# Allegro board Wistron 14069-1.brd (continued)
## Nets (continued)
GND: ATX1.3 ATX1.5 ATX1.7 ATX1.15 ATX1.17 ATX1.18 ATX1.19 ATX1.24 ATX2.1 ATX2.2 BT1.2 C2.2 C3.2 C6.2 C9.2 C11.2 C12.2 C13.2 C364.2 C365.2 C367.1 C371.2 C372.2 C420.1 C421.1 C422.1 C475.2 C476.2 C707.2 C708.2 C726.2 C727.2 C728.2 C729.2 C773.2 C774.2 C775.2 C1004.2 C1005.2 C1006.2 C1007.2 C1008.2 C1009.2 C1014.2 C1015.2 C1016.2 C1017.2 C1018.2 C1019.2 C1020.2 C1025.2 C1026.2 C1027.2 C1028.2 C1030.2 C1031.2 C1032.2 C1033.2 C1034.2 C1037.2 C1038.2 C1039.2 C1040.2 C1041.2 C1042.2 C1043.2 C1044.2 C1045.2 C1046.2 C1047.2 C1048.2 C1049.1 C1050.2 C1051.2 C1052.2 C1053.2 C1054.2 C1055.2 C1056.2 C1057.2 C1058.2 C1059.2 C1060.2 C1061.2 C1062.2 C1063.2 C1064.2 C1065.2 C1066.2 C1067.2 C1068.2 C1069.2 C1070.2 C1071.2 C1072.2 C1073.2 C1074.2 C1075.2 C1077.2 C1079.2 C1081.2 C1084.2 C1085.2 C1086.2 C1087.2 C1088.2 C1089.2 C1091.2 C1092.2 C1093.2 C1095.2 C1096.2 C1097.2 C1098.2 C1099.2 C1100.2 C1101.2 C1102.2 C1103.2 C1106.2 C1107.2 C1108.2 C1109.2 C1110.2 C1111.2 C1112.2 C1113.2 C1122.2 C1123.2 C1124.2 C1125.2 C1126.2 C1127.2 C1128.2 C1129.2 C1130.2 C1131.2 C1132.2 C1133.2 C1135.2 C1136.2 C1137.2 C1138.2 C1139.2 C1140.2 C1141.2 C1142.2 C1143.2 C1144.2 C1145.2 C1146.2 C1201.2 C1202.2 C1203.2 C1204.2 C1205.2 C1207.2 C1208.2 C1209.2 C1210.2 C1211.2 C1212.2 C1213.2 C1214.2 C1215.2 C1216.2 C1217.2 C1218.2 C1219.2 C1220.2 C1301.2 C1302.2 C1303.2 C1304.2 C1305.2 C1306.2 C1307.2 C1308.2 C1309.2 C1310.2 C1311.2 C1312.2 C1313.2 C1314.2 C1315.2 C1401.2 C1404.2 C1405.2 C1406.2 C1407.2 C1408.2 C1409.2 C1410.2 C1411.2 C1412.2 C1413.2 C1414.2 C1415.2 C1416.2 C1417.2 C1701.2 C1801.2 C1802.2 C1803.2 C1804.2 C2001.1 C2002.2 C2003.1 C2004.1 C2006.1 C2007.2 C2008.2 C2038.2 C2101.2 C2301.1 C2302.2 C2303.2 C2304.2 C2305.2 C2306.2 C2307.2 C2308.2 C2309.2 C2310.2 C2311.2 C2312.2 C2313.2 C2314.2 C2315.2 C2316.2 C2317.2 C2318.2 C2319.2 C2320.2 C2321.2 C2322.2 C2501.2 C2503.1 C2504.2 C2601.2 C2602.2 C2603.2 C2604.2 C2605.2 C2712.2 C2713.2 C2717.1 C2718.1 C2719.1 C2720.1 C2721.2 C2722.2 C2723.1 C2728.2 C2729.2 C2732.2 C2912.2 C2932.2 C3101.1 C3102.2 C3103.2 C3104.2 C3105.2 C3106.2 C3107.2 C3108.2 C3109.2 C3110.2 C3111.2 C3112.2 C3113.2 C3114.2 C3115.2 C3116.1 C3121.2 C3123.2 C3124.2 C3140.2 C3141.2 C3142.2 C3143.2 C3201.2 C3202.2 C3204.2 C3205.2 C3206.2 C3207.2 C3401.2 C3402.1 C3403.2 C3506.2 C3601.2 C3605.2 C3606.2 C3701.2 C3702.2 C3703.2 C3704.2 C3705.2 C3706.2 C3708.2 C3709.2 C3710.2 C3714.2 C3715.2 C3801.2 C3802.2 C3803.2 C3804.2 C3805.2 C3806.2 C3807.2 C3809.2 C3810.2 C3811.2 C3812.2 C3813.2 C3901.2 C3902.2 C3903.2 C3904.2 C4301.2 C4302.1 C4303.2 C4304.1 C4305.1 C4306.1 C4307.2 C4308.2 C4309.2 C4310.2 C4311.2 C5609.1 C5610.1 C5611.1 C5612.2 C5613.2 C5701.2 C5712.2 C5713.2 C6110.2 C6111.2 C6112.2 C6113.2 C6214.2 C6401.2 C6402.2 C6403.1 C6404.1 C6405.1 C6406.2 C7902.2 C7903.2 C7904.2 C7905.2 C7906.2 C7907.2 C7909.2 C7915.2 C7916.2 C7917.2 C7918.1 C7919.2 C7920.2 C7921.1 C9310.2 C9311.2 C9312.2 C9321.2 C9322.2 C9329.2 C9330.2 C9402.2 C9403.2 C9404.2 C9405.2 C9406.2 C9407.2 C9408.2 C9409.2 C9410.2 C9411.2 C9412.2 C9413.2 C9414.2 C9415.2 C9420.2 C9422.2 C9902.1 C15159.2 C15160.2 C15161.2 CPU1.A4 CPU1.A7 CPU1.A11 CPU1.A13 CPU1.A15 CPU1.A17 CPU1.A24 CPU1.AA3 CPU1.AA8 CPU1.AA33 CPU1.AB5 CPU1.AB39 CPU1.AC3 CPU1.AC6 CPU1.AC33 CPU1.AC34 CPU1.AC35 CPU1.AD1 CPU1.AD4 CPU1.AD6 CPU1.AD7 CPU1.AD8 CPU1.AD33 CPU1.AD36 CPU1.AD37 CPU1.AD38 CPU1.AD39 CPU1.AD40 CPU1.AE3 CPU1.AE5 CPU1.AE8 CPU1.AE33 CPU1.AE36 CPU1.AF1 CPU1.AF5 CPU1.AF8 CPU1.AF33 CPU1.AF36 CPU1.AF37 CPU1.AF40 CPU1.AG1 CPU1.AG2 CPU1.AG3 CPU1.AG4 CPU1.AG5 CPU1.AG8 CPU1.AG33 CPU1.AG36 CPU1.AH5 CPU1.AH8 CPU1.AH33 CPU1.AH36 CPU1.AH37 CPU1.AH38 CPU1.AH39 CPU1.AH40 CPU1.AJ1 CPU1.AJ4 CPU1.AJ5 CPU1.AJ8 CPU1.AJ31 CPU1.AJ32 CPU1.AJ33 CPU1.AJ34 CPU1.AJ35 CPU1.AJ36 CPU1.AK5 CPU1.AK6 CPU1.AK7 CPU1.AK8 CPU1.AK9 CPU1.AK10 CPU1.AK12 CPU1.AK13 CPU1.AK15 CPU1.AK16 CPU1.AK17 CPU1.AK18 CPU1.AK19 CPU1.AK20 CPU1.AK23 CPU1.AK25 CPU1.AK26 CPU1.AK28 CPU1.AK29 CPU1.AK30 CPU1.AK36 CPU1.AK37 CPU1.AK40 CPU1.AL1 CPU1.AL2 CPU1.AL3 CPU1.AL4 CPU1.AL5 CPU1.AL11 CPU1.AL14 CPU1.AL21 CPU1.AL24 CPU1.AL27 CPU1.AL30 CPU1.AL36 CPU1.AM5 CPU1.AM11 CPU1.AM14 CPU1.AM17 CPU1.AM19 CPU1.AM24 CPU1.AM27 CPU1.AM30 CPU1.AM31 CPU1.AM32 CPU1.AM33 CPU1.AM34 CPU1.AM35 CPU1.AM36 CPU1.AM37 CPU1.AM38 CPU1.AM39 CPU1.AM40 CPU1.AN1 CPU1.AN4 CPU1.AN5 CPU1.AN6 CPU1.AN7 CPU1.AN8 CPU1.AN9 CPU1.AN10 CPU1.AN11 CPU1.AN14 CPU1.AN16 CPU1.AN19 CPU1.AN22 CPU1.AN23 CPU1.AN24 CPU1.AN27 CPU1.AN30 CPU1.AN36 CPU1.AP5 CPU1.AP11 CPU1.AP14 CPU1.AP24 CPU1.AP27 CPU1.AP30 CPU1.AP36 CPU1.AP37 CPU1.AP40 CPU1.AR1 CPU1.AR2 CPU1.AR3 CPU1.AR4 CPU1.AR5 CPU1.AR11 CPU1.AR14 CPU1.AR16 CPU1.AR17 CPU1.AR18 CPU1.AR19 CPU1.AR20 CPU1.AR21 CPU1.AR22 CPU1.AR23 CPU1.AR24 CPU1.AR27 CPU1.AR30 CPU1.AR31 CPU1.AR32 CPU1.AR33 CPU1.AR34 CPU1.AR35 CPU1.AR36 CPU1.AT5 CPU1.AT6 CPU1.AT7 CPU1.AT8 CPU1.AT9 CPU1.AT10 CPU1.AT11 CPU1.AT12 CPU1.AT13 CPU1.AT14 CPU1.AT15 CPU1.AT17 CPU1.AT24 CPU1.AT25 CPU1.AT26 CPU1.AT27 CPU1.AT28 CPU1.AT29 CPU1.AT30 CPU1.AT31 CPU1.AT32 CPU1.AT34 CPU1.AT36 CPU1.AT37 CPU1.AT38 CPU1.AT39 CPU1.AT40 CPU1.AU1 CPU1.AU4 CPU1.AU5 CPU1.AU7 CPU1.AU25 CPU1.AU30 CPU1.AU34 CPU1.AV2 CPU1.AV5 CPU1.AV9 CPU1.AV26 CPU1.AV28 CPU1.AV30 CPU1.AV34 CPU1.AV38 CPU1.AW3 CPU1.AW5 CPU1.AW9 CPU1.AW30 CPU1.AW32 CPU1.AW34 CPU1.AW36 CPU1.AY3 CPU1.AY5 CPU1.AY7 CPU1.AY9 CPU1.AY27 CPU1.AY30 CPU1.B6 CPU1.B24 CPU1.B26 CPU1.B28 CPU1.B30 CPU1.B38 CPU1.C2 CPU1.C5 CPU1.C8 CPU1.C10 CPU1.C12 CPU1.C14 CPU1.C16 CPU1.C18 CPU1.C20 CPU1.C22 CPU1.C24 CPU1.C31 CPU1.C33 CPU1.C35 CPU1.C37 CPU1.D4 CPU1.D7 CPU1.D24 CPU1.D26 CPU1.D28 CPU1.D30 CPU1.D37 CPU1.D39 CPU1.D40 CPU1.E3 CPU1.E6 CPU1.E9 CPU1.E11 CPU1.E13 CPU1.E15 CPU1.E17 CPU1.E19 CPU1.E21 CPU1.E23 CPU1.E31 CPU1.E33 CPU1.E35 CPU1.E37 CPU1.F1 CPU1.F4 CPU1.F7 CPU1.F10 CPU1.F22 CPU1.F26 CPU1.F28 CPU1.F30 CPU1.F40 CPU1.G3 CPU1.G6 CPU1.G8 CPU1.G11 CPU1.G13 CPU1.G15 CPU1.G17 CPU1.G19 CPU1.G22 CPU1.G31 CPU1.G33 CPU1.H1 CPU1.H4 CPU1.H7 CPU1.H8 CPU1.H9 CPU1.H21 CPU1.H24 CPU1.H26 CPU1.H28 CPU1.H30 CPU1.H35 CPU1.H37 CPU1.H39 CPU1.J3 CPU1.J6 CPU1.J10 CPU1.J12 CPU1.J16 CPU1.J18 CPU1.J20 CPU1.J32 CPU1.J34 CPU1.K1 CPU1.K4 CPU1.K7 CPU1.K14 CPU1.K15 CPU1.K17 CPU1.K19 CPU1.K22 CPU1.K24 CPU1.K26 CPU1.K28 CPU1.K30 CPU1.K33 CPU1.K35 CPU1.K37 CPU1.K39 CPU1.L3 CPU1.L6 CPU1.L9 CPU1.L11 CPU1.L13 CPU1.L32 CPU1.M1 CPU1.M4 CPU1.M7 CPU1.M10 CPU1.M12 CPU1.M15 CPU1.M17 CPU1.M19 CPU1.M21 CPU1.M23 CPU1.M25 CPU1.M27 CPU1.M29 CPU1.M35 CPU1.M37 CPU1.M39 CPU1.N3 CPU1.N6 CPU1.N8 CPU1.N33 CPU1.P1 CPU1.P4 CPU1.P35 CPU1.P37 CPU1.P39 CPU1.R3 CPU1.R6 CPU1.R8 CPU1.R33 CPU1.T1 CPU1.T4 CPU1.T35 CPU1.T37 CPU1.T39 CPU1.U3 CPU1.U6 CPU1.U33 CPU1.V1 CPU1.V8 CPU1.V35 CPU1.V37 CPU1.V39 CPU1.W3 CPU1.W6 CPU1.W33 CPU1.Y5 CPU1.Y35 CPU1.Y37 CRF1.2 D2702.K DBGH1.8 DBGH1.12 DIMM1.2 DIMM1.4 DIMM1.6 DIMM1.9 DIMM1.11 DIMM1.13 DIMM1.15 DIMM1.17 DIMM1.20 DIMM1.22 DIMM1.24 DIMM1.26 DIMM1.28 DIMM1.31 DIMM1.33 DIMM1.35 DIMM1.37 DIMM1.39 DIMM1.42 DIMM1.44 DIMM1.46 DIMM1.48 DIMM1.50 DIMM1.53 DIMM1.55 DIMM1.57 DIMM1.94 DIMM1.96 DIMM1.98 DIMM1.101 DIMM1.103 DIMM1.105 DIMM1.107 DIMM1.109 DIMM1.112 DIMM1.114 DIMM1.116 DIMM1.118 DIMM1.120 DIMM1.123 DIMM1.125 DIMM1.127 DIMM1.129 DIMM1.131 DIMM1.134 DIMM1.136 DIMM1.138 DIMM1.140 DIMM1.147 DIMM1.149 DIMM1.151 DIMM1.154 DIMM1.156 DIMM1.158 DIMM1.160 DIMM1.162 DIMM1.165 DIMM1.167 DIMM1.169 DIMM1.171 DIMM1.173 DIMM1.176 DIMM1.178 DIMM1.180 DIMM1.182 DIMM1.184 DIMM1.187 DIMM1.189 DIMM1.191 DIMM1.193 DIMM1.195 DIMM1.198 DIMM1.200 DIMM1.202 DIMM1.238 DIMM1.239 DIMM1.241 DIMM1.243 DIMM1.246 DIMM1.248 DIMM1.250 DIMM1.252 DIMM1.254 DIMM1.257 DIMM1.259 DIMM1.261 DIMM1.263 DIMM1.265 DIMM1.268 DIMM1.270 DIMM1.272 DIMM1.274 DIMM1.276 DIMM1.279 DIMM1.281 DIMM1.283 DIMM2.2 DIMM2.4 DIMM2.6 DIMM2.9 DIMM2.11 DIMM2.13 DIMM2.15 DIMM2.17 DIMM2.20 DIMM2.22 DIMM2.24 DIMM2.26 DIMM2.28 DIMM2.31 DIMM2.33 DIMM2.35 DIMM2.37 DIMM2.39 DIMM2.42 DIMM2.44 DIMM2.46 DIMM2.48 DIMM2.50 DIMM2.53 DIMM2.55 DIMM2.57 DIMM2.94 DIMM2.96 DIMM2.98 DIMM2.101 DIMM2.103 DIMM2.105 DIMM2.107 DIMM2.109 DIMM2.112 DIMM2.114 DIMM2.116 DIMM2.118 DIMM2.120 DIMM2.123 DIMM2.125 DIMM2.127 DIMM2.129 DIMM2.131 DIMM2.134 DIMM2.136 DIMM2.138 DIMM2.147 DIMM2.149 DIMM2.151 DIMM2.154 DIMM2.156 DIMM2.158 DIMM2.160 DIMM2.162 DIMM2.165 DIMM2.167 DIMM2.169 DIMM2.171 DIMM2.173 DIMM2.176 DIMM2.178 DIMM2.180 DIMM2.182 DIMM2.184 DIMM2.187 DIMM2.189 DIMM2.191 DIMM2.193 DIMM2.195 DIMM2.198 DIMM2.200 DIMM2.202 DIMM2.238 DIMM2.239 DIMM2.241 DIMM2.243 DIMM2.246 DIMM2.248 DIMM2.250 DIMM2.252 DIMM2.254 DIMM2.257 DIMM2.259 DIMM2.261 DIMM2.263 DIMM2.265 DIMM2.268 DIMM2.270 DIMM2.272 DIMM2.274 DIMM2.276 DIMM2.279 DIMM2.281 DIMM2.283 DIMM3.2 DIMM3.4 DIMM3.6 DIMM3.9 DIMM3.11 DIMM3.13 DIMM3.15 DIMM3.17 DIMM3.20 DIMM3.22 DIMM3.24 DIMM3.26 DIMM3.28 DIMM3.31 DIMM3.33 DIMM3.35 DIMM3.37 DIMM3.39 DIMM3.42 DIMM3.44 DIMM3.46 DIMM3.48 DIMM3.50 DIMM3.53 DIMM3.55 DIMM3.57 DIMM3.94 DIMM3.96 DIMM3.98 DIMM3.101 DIMM3.103 DIMM3.105 DIMM3.107 DIMM3.109 DIMM3.112 DIMM3.114 DIMM3.116 DIMM3.118 DIMM3.120 DIMM3.123 DIMM3.125 DIMM3.127 DIMM3.129 DIMM3.131 DIMM3.134 DIMM3.136 DIMM3.138 DIMM3.139 DIMM3.140 DIMM3.147 DIMM3.149 DIMM3.151 DIMM3.154 DIMM3.156 DIMM3.158 DIMM3.160 DIMM3.162 DIMM3.165 DIMM3.167 DIMM3.169 DIMM3.171 DIMM3.173 DIMM3.176 DIMM3.178 DIMM3.180 DIMM3.182 DIMM3.184 DIMM3.187 DIMM3.189 DIMM3.191 DIMM3.193 DIMM3.195 DIMM3.198 DIMM3.200 DIMM3.202 DIMM3.238 DIMM3.239 DIMM3.241 DIMM3.243 DIMM3.246 DIMM3.248 DIMM3.250 DIMM3.252 DIMM3.254 DIMM3.257 DIMM3.259 DIMM3.261 DIMM3.263 DIMM3.265 DIMM3.268 DIMM3.270 DIMM3.272 DIMM3.274 DIMM3.276 DIMM3.279 DIMM3.281 DIMM3.283 DIMM4.2 DIMM4.4 DIMM4.6 DIMM4.9 DIMM4.11 DIMM4.13 DIMM4.15 DIMM4.17 DIMM4.20 DIMM4.22 DIMM4.24 DIMM4.26 DIMM4.28 DIMM4.31 DIMM4.33 DIMM4.35 DIMM4.37 DIMM4.39 DIMM4.42 DIMM4.44 DIMM4.46 DIMM4.48 DIMM4.50 DIMM4.53 DIMM4.55 DIMM4.57 DIMM4.94 DIMM4.96 DIMM4.98 DIMM4.101 DIMM4.103 DIMM4.105 DIMM4.107 DIMM4.109 DIMM4.112 DIMM4.114 DIMM4.116 DIMM4.118 DIMM4.120 DIMM4.123 DIMM4.125 DIMM4.127 DIMM4.129 DIMM4.131 DIMM4.134 DIMM4.136 DIMM4.138 DIMM4.139 DIMM4.147 DIMM4.149 DIMM4.151 DIMM4.154 DIMM4.156 DIMM4.158 DIMM4.160 DIMM4.162 DIMM4.165 DIMM4.167 DIMM4.169 DIMM4.171 DIMM4.173 DIMM4.176 DIMM4.178 DIMM4.180 DIMM4.182 DIMM4.184 DIMM4.187 DIMM4.189 DIMM4.191 DIMM4.193 DIMM4.195 DIMM4.198 DIMM4.200 DIMM4.202 DIMM4.238 DIMM4.239 DIMM4.241 DIMM4.243 DIMM4.246 DIMM4.248 DIMM4.250 DIMM4.252 DIMM4.254 DIMM4.257 DIMM4.259 DIMM4.261 DIMM4.263 DIMM4.265 DIMM4.268 DIMM4.270 DIMM4.272 DIMM4.274 DIMM4.276 DIMM4.279 DIMM4.281 DIMM4.283 DP1.2 DP1.5 DP1.8 DP1.11 DP1.16 DP1.19 DP1.X1 DP1.X2 DP1.X3 DP1.X4 ED3201.2 ED3203.2 ED3204.2 ED5601.3 ED5601.8 ED5602.3 ED5602.8 ED5603.3 ED5603.8 ED5701.3 ED5701.8 ED5702.3 ED5702.8 ED5703.3 ED5703.8 FANC1.1 FANS1.1 FANS2.1 FANS3.1 GPIO1.2 GPIO2.2 H1.1 H1.2 H1.3 H1.4 H1.5 H1.6 H1.7 H1.8 H2.1 H2.2 H2.3 H2.4 H2.5 H2.6 H2.7 H2.8 H3.1 H3.2 H3.3 H3.4 H3.5 H3.6 H3.7 H3.8 H4.1 H4.2 H4.3 H4.4 H4.5 H4.6 H4.7 H4.8 H5.1 H5.2 H5.3 H5.4 H5.5 H5.6 H5.7 H5.8 H7.1 H7.2 H7.3 H7.4 H7.5 H7.6 H7.7 H7.8 H8.1 H8.2 H8.3 H8.4 H8.5 H8.6 H8.7 H8.8 HDMI1.2 HDMI1.5 HDMI1.8 HDMI1.11 HDMI1.17 HDMI1.20 HDMI1.21 HDMI1.22 HDMI1.23 HS1.1 HS2.1 HS3.1 LEDH1.4 LEDH1.5 LEDH1.8 LEDH1.14 LEDH2.3 LEDH2.4 LEDH2.8 LEDH2.9 LEDH2.10 NGFFE1.1 NGFFE1.7 NGFFE1.18 NGFFE1.33 NGFFE1.39 NGFFE1.45 NGFFE1.51 NGFFE1.57 NGFFE1.63 NGFFE1.69 NGFFE1.75 NGFFM1.1 NGFFM1.3 NGFFM1.9 NGFFM1.15 NGFFM1.21 NGFFM1.27 NGFFM1.33 NGFFM1.39 NGFFM1.45 NGFFM1.51 NGFFM1.57 NGFFM1.71 NGFFM1.73 NGFFM1.75 NGFFM1.76 NGFFM1.77 PC301.2 PC4605.2 PC4606.2 PC4628.2 PC4632.2 PC4633.2 PC4634.2 PC4635.1 PC4636.1 PC4637.1 PC4639.2 PC4640.2 PC4642.2 PC4644.2 PC4645.2 PC4646.2 PC4655.2 PC4666.1 PC4701.2 PC4702.2 PC4704.2 PC4705.2 PC4707.2 PC4708.2 PC4709.2 PC4711.2 PC4712.2 PC4713.2 PC4716.2 PC4717.2 PC4735.2 PC4736.2 PC4737.2 PC4801.2 PC4803.2 PC4804.2 PC4805.2 PC4807.2 PC4808.2 PC4809.2 PC4810.2 PC5002.2 PC5003.2 PC5004.2 PC5006.2 PC5007.2 PC5009.2 PC5010.2 PC5011.2 PC5012.2 PC5020.2 PC5033.2 PC5034.2 PC5035.2 PC5036.2 PC5037.2 PC5040.2 PC5041.2 PC5101.2 PC5102.2 PC5103.2 PC5106.1 PC5108.2 PC5109.2 PC5111.1 PC5201.2 PC5202.2 PC5203.2 PC5204.2 PC5206.1 PC5211.2 PC5219.2 PC5301.2 PC5302.2 PC5303.2 PC5304.2 PC5306.2 PC5307.2 PC5308.2 PC5310.2 PC5311.2 PC5427.2 PC5438.2 PCH1.A2 PCH1.A3 PCH1.A4 PCH1.A18 PCH1.A25 PCH1.A32 PCH1.A37 PCH1.A42 PCH1.A44 PCH1.AA4 PCH1.AA17 PCH1.AA18 PCH1.AA20 PCH1.AA21 PCH1.AA25 PCH1.AA29 PCH1.AA42 PCH1.AB4 PCH1.AB5 PCH1.AB7 PCH1.AB8 PCH1.AB14 PCH1.AB15 PCH1.AB31 PCH1.AB32 PCH1.AB38 PCH1.AC1 PCH1.AC18 PCH1.AC20 PCH1.AC21 PCH1.AC25 PCH1.AC29 PCH1.AC45 PCH1.AD4 PCH1.AD8 PCH1.AD11 PCH1.AD14 PCH1.AD32 PCH1.AD33 PCH1.AD36 PCH1.AE4 PCH1.AE18 PCH1.AE20 PCH1.AE21 PCH1.AE25 PCH1.AE28 PCH1.AE29 PCH1.AE42 PCH1.AF18 PCH1.AF20 PCH1.AF21 PCH1.AF23 PCH1.AF25 PCH1.AF26 PCH1.AF28 PCH1.AF29 PCH1.AG4 PCH1.AG11 PCH1.AG13 PCH1.AG31 PCH1.AG32 PCH1.AG33 PCH1.AG38 PCH1.AH1 PCH1.AH17 PCH1.AH18 PCH1.AH20 PCH1.AH21 PCH1.AH23 PCH1.AH25 PCH1.AH26 PCH1.AH28 PCH1.AH29 PCH1.AH45 PCH1.AJ10 PCH1.AJ14 PCH1.AJ15 PCH1.AJ17 PCH1.AJ18 PCH1.AJ26 PCH1.AJ28 PCH1.AJ29 PCH1.AJ31 PCH1.AJ32 PCH1.AJ36 PCH1.AK4 PCH1.AK42 PCH1.AL4 PCH1.AL10 PCH1.AL11 PCH1.AL13 PCH1.AL17 PCH1.AL19 PCH1.AL24 PCH1.AL29 PCH1.AL32 PCH1.AL33 PCH1.AL38 PCH1.AM15 PCH1.AM17 PCH1.AM19 PCH1.AM22 PCH1.AM24 PCH1.AM27 PCH1.AM29 PCH1.AM45 PCH1.AN4 PCH1.AN7 PCH1.AN8 PCH1.AN10 PCH1.AN11 PCH1.AN22 PCH1.AN27 PCH1.AN31 PCH1.AN39 PCH1.AP4 PCH1.AP11 PCH1.AR5 PCH1.AR7 PCH1.AR9 PCH1.AR33 PCH1.AR34 PCH1.AR42 PCH1.AT9 PCH1.AT10 PCH1.AT15 PCH1.AT36 PCH1.AU1 PCH1.AU7 PCH1.AU35 PCH1.AU36 PCH1.AU39 PCH1.AU45 PCH1.AV6 PCH1.AV17 PCH1.AV24 PCH1.AV27 PCH1.AV31 PCH1.AV33 PCH1.AW9 PCH1.AW13 PCH1.AW19 PCH1.AW29 PCH1.AW37 PCH1.AY38 PCH1.AY45 PCH1.B1 PCH1.B2 PCH1.B3 PCH1.B6 PCH1.B25 PCH1.B37 PCH1.B40 PCH1.B44 PCH1.B45 PCH1.BA1 PCH1.BB1 PCH1.BB11 PCH1.BB16 PCH1.BB21 PCH1.BB25 PCH1.BB30 PCH1.BB34 PCH1.BC1 PCH1.BC2 PCH1.BD2 PCH1.BD43 PCH1.BD44 PCH1.BD45 PCH1.BE9 PCH1.BE14 PCH1.BE18 PCH1.BE23 PCH1.BE28 PCH1.BE32 PCH1.BE37 PCH1.BE40 PCH1.BE44 PCH1.C1 PCH1.C2 PCH1.C4 PCH1.C10 PCH1.C28 PCH1.C37 PCH1.C42 PCH1.D1 PCH1.D10 PCH1.D12 PCH1.D15 PCH1.D16 PCH1.D17 PCH1.D19 PCH1.D21 PCH1.D24 PCH1.D25 PCH1.D27 PCH1.D29 PCH1.D30 PCH1.D31 PCH1.D33 PCH1.D35 PCH1.D36 PCH1.D45 PCH1.E13 PCH1.E15 PCH1.E31 PCH1.E33 PCH1.F8 PCH1.F44 PCH1.G9 PCH1.G42 PCH1.H3 PCH1.H17 PCH1.H19 PCH1.H22 PCH1.H24 PCH1.H27 PCH1.H29 PCH1.H35 PCH1.J3 PCH1.J5 PCH1.J7 PCH1.J10 PCH1.J11 PCH1.J39 PCH1.K4 PCH1.K10 PCH1.K27 PCH1.K33 PCH1.K36 PCH1.K42 PCH1.K43 PCH1.L4 PCH1.L8 PCH1.L12 PCH1.L13 PCH1.L15 PCH1.L41 PCH1.M35 PCH1.M42 PCH1.N4 PCH1.N5 PCH1.N10 PCH1.N15 PCH1.N19 PCH1.N22 PCH1.N24 PCH1.N35 PCH1.N36 PCH1.N41 PCH1.P17 PCH1.P19 PCH1.P22 PCH1.P45 PCH1.R5 PCH1.R10 PCH1.R14 PCH1.R22 PCH1.R29 PCH1.R33 PCH1.R38 PCH1.T1 PCH1.T2 PCH1.T4 PCH1.T42 PCH1.U4 PCH1.U8 PCH1.U10 PCH1.U11 PCH1.U14 PCH1.U15 PCH1.U17 PCH1.U18 PCH1.U28 PCH1.U29 PCH1.U31 PCH1.U32 PCH1.U33 PCH1.U38 PCH1.V3 PCH1.V18 PCH1.V20 PCH1.V21 PCH1.V23 PCH1.V25 PCH1.V29 PCH1.V45 PCH1.W4 PCH1.W8 PCH1.W14 PCH1.W31 PCH1.W32 PCH1.W33 PCH1.W38 PCH1.Y17 PCH1.Y18 PCH1.Y20 PCH1.Y21 PCH1.Y26 PCH1.Y28 PCH1.Y29 PCIE1.A1 PCIE1.A4 PCIE1.A12 PCIE1.A15 PCIE1.A18 PCIE1.B4 PCIE1.B7 PCIE1.B13 PCIE1.B16 PCIE1.B18 PCIE2.A1 PCIE2.A4 PCIE2.A12 PCIE2.A15 PCIE2.A18 PCIE2.B4 PCIE2.B7 PCIE2.B13 PCIE2.B16 PCIE2.B18 PCIE16.A4 PCIE16.A12 PCIE16.A15 PCIE16.A18 PCIE16.A20 PCIE16.A23 PCIE16.A24 PCIE16.A27 PCIE16.A28 PCIE16.A31 PCIE16.A34 PCIE16.A37 PCIE16.A38 PCIE16.A41 PCIE16.A42 PCIE16.A45 PCIE16.A46 PCIE16.A49 PCIE16.A51 PCIE16.A54 PCIE16.A55 PCIE16.A58 PCIE16.A59 PCIE16.A62 PCIE16.A63 PCIE16.A66 PCIE16.A67 PCIE16.A70 PCIE16.A71 PCIE16.A74 PCIE16.A75 PCIE16.A78 PCIE16.A79 PCIE16.A82 PCIE16.B4 PCIE16.B7 PCIE16.B13 PCIE16.B16 PCIE16.B18 PCIE16.B21 PCIE16.B22 PCIE16.B25 PCIE16.B26 PCIE16.B29 PCIE16.B32 PCIE16.B35 PCIE16.B36 PCIE16.B39 PCIE16.B40 PCIE16.B43 PCIE16.B44 PCIE16.B47 PCIE16.B49 PCIE16.B52 PCIE16.B53 PCIE16.B56 PCIE16.B57 PCIE16.B60 PCIE16.B61 PCIE16.B64 PCIE16.B65 PCIE16.B68 PCIE16.B69 PCIE16.B72 PCIE16.B73 PCIE16.B76 PCIE16.B77 PCIE16.B80 PR4601.2 PR4643.2 PR4647.2 PR4655.2 PR4659.1 PR4673.1 PR4674.1 PR4675.1 PR4677.1 PR4683.2 PR4685.1 PR4688.1 PR4741.1 PR4743.1 PR4745.1 PR4747.1 PR4825.1 PR4827.1 PR5018.2 PR5109.2 PR5110.2 PR5118.2 PR5145.2 PR5146.2 PR5207.2 PR5211.2 PR5216.2 PR5307.2 PR5308.2 PR5317.2 PR5458.1 PT1.2 PT2.2 PT4701.2 PT4702.2 PT4703.2 PT4704.2 PT4705.2 PT4706.2 PT4707.2 PT4708.2 PT4709.2 PT4801.2 PT4802.2 PT4803.2 PT4804.2 PT4805.2 PT4806.2 PT4807.2 PT5004.2 PT5101.2 PT5107.2 PT5201.2 PT5202.2 PT5203.2 PT5204.2 PU51.11 PU4002.S PU4003.S PU4601.57 PU4705.1 PU4705.2 PU4705.3 PU4706.1 PU4706.2 PU4706.3 PU4707.1 PU4707.2 PU4707.3 PU4709.2 PU4709.9 PU4710.1 PU4710.2 PU4710.3 PU4711.1 PU4711.2 PU4711.3 PU4713.2 PU4713.9 PU4714.1 PU4714.2 PU4714.3 PU4715.1 PU4715.2 PU4715.3 PU4716.2 PU4716.9 PU4717.1 PU4717.2 PU4717.3 PU4719.2 PU4719.9 PU4801.1 PU4801.2 PU4801.3 PU4804.2 PU4804.9 PU4805.1 PU4805.2 PU4805.3 PU4806.1 PU4806.2 PU4806.3 PU4809.2 PU4809.9 PU4810.1 PU4810.2 PU4810.3 PU5001.1 PU5001.2 PU5001.3 PU5002.1 PU5002.3 PU5002.14 PU5002.21 PU5101.11 PU5103.1 PU5103.2 PU5103.3 PU5201.1 PU5201.2 PU5201.3 PU5202.7 PU5202.16 PU5202.17 PU5301.11 PU5303.1 PU5303.2 PU5303.3 Q1.1 Q1.4 Q23.1 Q23.4 Q25.1 Q25.4 Q58.S Q72.1 Q72.4 Q73.E Q98.S Q2002.E Q2702.C Q2703.C Q2705.C Q3103.1 Q3103.4 Q3107.E Q3401.S Q3402.S Q3512.S Q3514.S Q3516.S Q3518.S Q4301.S Q4302.S Q4303.S Q4304.S Q5602.S Q5702.1 Q5702.4 Q6402.1 Q6402.4 Q6807.S R79.1 R80.2 R81.2 R82.2 R83.2 R91.1 R403.2 R407.2 R415.2 R416.2 R417.2 R418.2 R419.2 R420.2 R423.2 R424.2 R425.2 R426.2 R427.2 R428.2 R429.2 R430.2 R431.2 R432.2 R448.2 R458.2 R508.2 R531.2 R806.2 R807.2 R811.2 R813.2 R814.2 R879.2 R901.2 R1123.2 R1129.1 R1205.1 R1207.2 R1604.2 R1605.2 R1606.2 R1610.1 R1615.2 R1617.2 R1619.2 R1706.2 R2010.2 R2031.1 R2037.1 R2048.2 R2054.1 R2056.1 R2107.1 R2110.1 R2203.1 R2205.1 R2207.1 R2209.1 R2211.1 R2213.1 R2215.1 R2218.1 R2220.1 R2222.1 R2224.1 R2225.1 R2227.1 R2406.1 R2479.2 R2516.2 R2606.2 R2617.2 R2620.2 R2624.2 R2631.2 R2701.1 R2705.1 R2706.1 R2707.1 R2715.2 R3102.1 R3118.1 R3120.1 R3158.2 R3409.1 R3410.1 R3411.1 R3415.2 R3417.2 R3604.2 R3702.2 R3704.2 R3706.2 R3814.2 R3816.2 R3914.2 R3919.2 R3920.1 R4020.1 R4026.1 R5205.2 R5615.1 R5701.2 R5706.2 R5708.2 R5709.2 R5710.2 R5714.2 R6116.1 R6117.1 R7943.2 R7954.2 R9301.1 R9901.2 R9916.2 R31132.2 SATA2.1 SATA2.4 SATA2.7 SATA2.8 SATA2.9 SATA3.1 SATA3.4 SATA3.7 SATA3.8 SATA3.9 SATA4.1 SATA4.4 SATA4.7 SATA4.8 SATA4.9 SATA5.1 SATA5.4 SATA5.7 SATA5.8 SATA5.9 SATAEX1.19 SATAEX1.20 SATAEX1.S1 SATAEX1.S4 SATAEX1.S7 SATAEX1.S8 SATAEX1.S11 SATAEX1.S14 SIO1.7 SIO1.38 SIO1.74 SPI1.4 TC5.2 TC2601.2 TC2602.2 TC3401.2 TC3601.2 TC3701.2 TC3702.2 TC3801.2 TC3802.2 TC3901.2 TC5002.2 TC5003.2 TC5301.2 TC9302.2 TC9401.2 TC9402.2 U2.1 U2.4 U2RJ1.G1 U2RJ1.G2 U2RJ1.G3 U2RJ1.G4 U2RJ1.G5 U2RJ1.G6 U2RJ1.G7 U2RJ1.G8 U2RJ1.R10 U2RJ1.U4 U2RJ1.U8 U5.1 U5.4 U25.1 U25.4 U26.1 U26.4 U27.1 U27.4 U28.1 U28.4 U62.3 U63.3 U401.S U402.S U403.S U404.S U2501.4 U2701.7 U3101.33 U3401.14 U3401.17 U3601.3 U3602.2 U3603.3 U3604.3 U3605.2 U3606.2 U3607.3 U3608.2 U3701.2 U3702.2 U3801.3 U3801.8 U3802.3 U3802.8 U3803.2 U3804.2 U3805.3 U3805.8 U3806.3 U3806.8 U3901.3 U3901.8 U3902.3 U3902.8 U3903.2 U4002.7 U5202.S U5203.S U7902.4 USB2F2.2 USB2F2.3 USB2F2.4 USB3F1.4 USB3F1.7 USB3F1.13 USB3F1.16 USB3R1.4 USB3R1.7 USB3R1.13 USB3R1.16 USB3R1.19 USB3R1.20 USB3R1.21 USB3R1.22 USB3R2.4 USB3R2.7 USB3R2.13 USB3R2.16 USB3R2.19 USB3R2.20 USB3R2.21 USB3R2.22 WP1.3 WPWR1.2 X1801.2 X1801.3 X1802.2 X1802.4 X3101.2 X3101.4 XDP1.2 XDP1.7 XDP1.8 XDP1.13 XDP1.14 XDP1.19 XDP1.20 XDP1.25 XDP1.26 XDP1.31 XDP1.32 XDP1.37 XDP1.38 XDP1.49 XDP1.50 XDP1.59
VBAT_SIO: C7902.1 R7925.1 SIO1.69
VCC3_3SBREF: R507.2 R508.1 U16.1
VCC_EOPIO: CPU1.AJ25 CPU1.AJ26 R811.1 TP_CPU2.1
VCC_GTX: CPU1.F35 CPU1.G34 CPU1.G35 CPU1.H33 CPU1.H34 CPU1.J33 CPU1.J35 CPU1.K32 CPU1.K34 CPU1.L31 CPU1.L33 CPU1.M32 R806.1 TP_CPU4.1
VCC_OPC: CPU1.AJ27 CPU1.AJ28 CPU1.AJ29 CPU1.AJ30 CPU1.AK27 R807.1 TP_CPU1.1
VCC_OPC_DP8: CPU1.AB37 TP_CPU3.1
VCC_ST: C5.2 C1048.1 C1049.2 CPU1.V4 CPU1.V5 PC4635.2 PR4678.1 PR4679.1 PR4680.2 PR4681.1 Q2.S R76.1 R83.1 R404.2 R408.2 R421.2 R470.2 R471.2 R704.2 R1707.2 R2035.2 R2038.2 R2040.2 R2043.2
VCCCORE_SENSE: CPU1.C38 PC4639.1 PC4641.1 PR4616.1 PR5413.1 PU4601.12
VCCGT_GAP1: PG4801.2 PR4820.1
VCCGT_GAP2: PG4803.2 PR4822.1
VCCGT_SENSE: CPU1.F39 PC4642.1 PC4643.1 PR4633.1 PR4635.1 PU4601.33
VCCIO_3P3V_EN: C372.1 R525.2 U26.2
VCCIO_3P3V_EN_C: R530.2 U26.5 U26.6
VCCIO_12V_EN: C371.1 R523.2 R531.1 U25.2
VCCIO_12V_EN_C: R524.2 U25.5 U25.6
VCCIO_EN: PR5301.2 R532.1 R533.1 R696.2 R888.2 R4017.1 U25.3 U26.3
VCCIO_EN_C: R696.1 U27.3
VCCIO_EN_R: R477.2 R4017.2 U4002.11
VCCIO_PWRGD: PR5304.2 PR5320.1 PU5301.1
VCCIO_SENSE: CPU1.AF4 PR5318.1
VCCIO_SENSE_1: PR5310.2 PR5312.1 PR5318.2
VCCSA_IO_SSENSE: CPU1.AE4 R804.1 R805.1
VCCSA_PGOOD: D20.2 PC5219.1 PR5204.2 PU5202.6
VCCSA_SENSE: CPU1.AD5 PR5213.2 PR5214.2 PR5215.2
VDDQ_BLEED: R4024.2 U4002.8
VDDQ_EN: C708.1 PU5002.8 R983.1 R4016.2 R4021.2 R4022.2
VDDQ_EN_CR: R983.2 U62.4
VDDQ_EN_R: R4016.1 U4002.9
VDDQ_R: R405.1 U5.3
VDDQ_S3_PG: PR5009.2 PU5002.10 R532.2
VSS_VCCIO_SENSE_1: PR5316.2 PR5317.1 PR5319.2
VSS_VCCIO_SSENSE: PR5319.1 R805.2
VSS_VCCSA_SSENSE: PR5216.1 PU5202.11 R804.2
VSSCORE_SENSE: CPU1.D38 PC4640.1 PC4641.2 PR4685.2 PU4601.13
VSSGT_SENSE: CPU1.F38 PR4689.1
0D6V_VTT: C1102.1 C1103.1 C1207.1 C1208.1 C1310.1 C1311.1 C1412.1 C1413.1 DIMM1.77 DIMM1.221 DIMM2.77 DIMM2.221 DIMM3.77 DIMM3.221 DIMM4.77 DIMM4.221 PR5013.1
0D95V_VCCIO_S0: C11.1 C12.1 C13.1 C1124.1 C1125.1 C1126.1 C1129.1 CPU1.AJ23 CPU1.AK11 CPU1.AK14 CPU1.AK24 CPU1.M8 CPU1.P8 CPU1.T8 CPU1.U8 CPU1.W8 PR4682.2 PR5313.2 PR5314.2 PR5315.2 PR5321.2 R302.1 R703.2 R9913.1
0D95V_VCCSA_S0: C1099.1 C1100.1 C1127.1 C1128.1 CPU1.AA6 CPU1.AA7 CPU1.AB6 CPU1.AB7 CPU1.AB8 CPU1.AC7 CPU1.AC8 CPU1.N7 CPU1.P7 CPU1.R7 CPU1.T7 CPU1.U7 CPU1.V7 CPU1.W7 CPU1.Y6 CPU1.Y7 CPU1.Y8 PC5206.2 PG5202.1 PL5203.2 PR5214.1 PT5202.1 PT5203.1 PT5204.1
1D2V_VDDQ_S3: C1050.1 C1051.1 C1052.1 C1053.1 C1091.1 C1092.1 C1093.1 C1095.1 C1096.1 C1097.1 C1098.1 C1101.1 C1106.1 C1107.1 C1108.1 C1109.1 C1110.1 C1111.1 C1112.1 C1113.1 C1138.1 C1201.1 C1202.1 C1209.1 C1210.1 C1211.1 C1212.1 C1213.1 C1214.1 C1215.1 C1216.1 C1301.1 C1302.1 C1303.1 C1304.1 C1305.1 C1306.1 C1307.1 C1308.1 C1309.1 C1401.1 C1404.1 C1405.1 C1406.1 C1407.1 C1408.1 C1409.1 C1410.1 C1411.1 CPU1.AT18 CPU1.AT21 CPU1.AU13 CPU1.AU15 CPU1.AU19 CPU1.AU23 CPU1.AV11 CPU1.AV17 CPU1.AV21 CPU1.AW10 CPU1.AW14 CPU1.AW25 CPU1.AY12 CPU1.AY16 CPU1.AY18 CPU1.AY23 DIMM1.7 DIMM1.18 DIMM1.29 DIMM1.40 DIMM1.51 DIMM1.59 DIMM1.61 DIMM1.64 DIMM1.67 DIMM1.70 DIMM1.73 DIMM1.76 DIMM1.80 DIMM1.83 DIMM1.85 DIMM1.88 DIMM1.90 DIMM1.92 DIMM1.99 DIMM1.110 DIMM1.121 DIMM1.132 DIMM1.204 DIMM1.206 DIMM1.209 DIMM1.212 DIMM1.215 DIMM1.217 DIMM1.220 DIMM1.223 DIMM1.226 DIMM1.229 DIMM1.231 DIMM1.233 DIMM1.236 DIMM2.7 DIMM2.18 DIMM2.29 DIMM2.40 DIMM2.51 DIMM2.59 DIMM2.61 DIMM2.64 DIMM2.67 DIMM2.70 DIMM2.73 DIMM2.76 DIMM2.80 DIMM2.83 DIMM2.85 DIMM2.88 DIMM2.90 DIMM2.92 DIMM2.99 DIMM2.110 DIMM2.121 DIMM2.132 DIMM2.204 DIMM2.206 DIMM2.209 DIMM2.212 DIMM2.215 DIMM2.217 DIMM2.220 DIMM2.223 DIMM2.226 DIMM2.229 DIMM2.231 DIMM2.233 DIMM2.236 DIMM3.7 DIMM3.18 DIMM3.29 DIMM3.40 DIMM3.51 DIMM3.59 DIMM3.61 DIMM3.64 DIMM3.67 DIMM3.70 DIMM3.73 DIMM3.76 DIMM3.80 DIMM3.83 DIMM3.85 DIMM3.88 DIMM3.90 DIMM3.92 DIMM3.99 DIMM3.110 DIMM3.121 DIMM3.132 DIMM3.204 DIMM3.206 DIMM3.209 DIMM3.212 DIMM3.215 DIMM3.217 DIMM3.220 DIMM3.223 DIMM3.226 DIMM3.229 DIMM3.231 DIMM3.233 DIMM3.236 DIMM4.7 DIMM4.18 DIMM4.29 DIMM4.40 DIMM4.51 DIMM4.59 DIMM4.61 DIMM4.64 DIMM4.67 DIMM4.70 DIMM4.73 DIMM4.76 DIMM4.80 DIMM4.83 DIMM4.85 DIMM4.88 DIMM4.90 DIMM4.92 DIMM4.99 DIMM4.110 DIMM4.121 DIMM4.132 DIMM4.204 DIMM4.206 DIMM4.209 DIMM4.212 DIMM4.215 DIMM4.217 DIMM4.220 DIMM4.223 DIMM4.226 DIMM4.229 DIMM4.231 DIMM4.233 DIMM4.236 PR5016.2 PR5017.2 PR5019.2 PR5020.2 PR5022.2 PR5023.2 PT1.1 PT2.1 R155.1 R405.2 R802.2 R1117.1 R1118.1 R1119.1 R1130.1 R1132.1 R1204.1 R2053.1 U4002.6
1D05V_VLAN: C3107.1 C3108.1 C3109.1 C3110.1 C3111.1 C3112.1 C3114.1 C3115.1 L3101.2 R3103.2 U3101.3 U3101.8 U3101.22 U3101.30
1D05V_VLANOUT: C3106.1 L3101.1 R3103.1 U3101.24
2D5V_VPP_S3: C1130.1 C1131.1 C1219.1 C1220.1 C1314.1 C1315.1 C1416.1 C1417.1 DIMM1.142 DIMM1.143 DIMM1.286 DIMM1.287 DIMM1.288 DIMM2.142 DIMM2.143 DIMM2.286 DIMM2.287 DIMM2.288 DIMM3.142 DIMM3.143 DIMM3.286 DIMM3.287 DIMM3.288 DIMM4.142 DIMM4.143 DIMM4.286 DIMM4.287 DIMM4.288 PR5026.2 PR5027.2 R2938.1 R2939.1 R4010.2
3.3_POP: Q2702.E Q2703.B Q2705.E R2711.1
3D3V_1D8V_PCHSPI_S5: PCH1.BE41 PCH1.BE42 PCH1.BE43 R2109.1 R2202.1 R2204.1 R2206.1 R2208.1
3D3V_AUX_EN: C3510.2 C15160.1 Q9303.4 R4202.1
3D3V_AUX_EN_12V: C3511.2 C15161.1 Q9303.2 R4203.1
3D3V_DPPWR_S0: C5712.1 C5713.1 DP1.20 F5602.2
3D3V_DPPWR_S0_F: F5602.1 Q5705.S
3D3V_DVDDIO_AUDIO: C2322.1 PCH1.BA15 R2108.2
3D3V_LAN: C3104.1 C3105.1 C3123.1 C3124.1 C3204.1 C3205.1 C3207.1 ED3201.5 ED3203.5 ED3204.5 Q3106.D R79.2 R3101.2 R3113.2 R3164.2 R3165.1 R3166.2 U2RJ1.L4 U3101.11 U3101.32 U3102.G
3D3V_S0: ATX1.1 ATX1.2 ATX1.12 ATX1.13 C421.2 C422.2 C475.1 C476.1 C726.1 C727.1 C728.1 C729.1 C1122.1 C1123.1 C1217.1 C1218.1 C1312.1 C1313.1 C1414.1 C1415.1 C2316.1 C2713.1 C2728.1 C2729.1 C3511.1 C4309.1 C9329.1 C9330.1 C9406.1 C9407.1 C9408.1 C9409.1 C9410.1 C9415.1 D2601.K D2602.K D2603.K DBGH1.14 DIMM1.139 DIMM1.284 DIMM2.139 DIMM2.140 DIMM2.284 DIMM3.284 DIMM4.140 DIMM4.284 NGFFM1.2 NGFFM1.4 NGFFM1.12 NGFFM1.14 NGFFM1.16 NGFFM1.18 NGFFM1.70 NGFFM1.72 NGFFM1.74 PCH1.AD13 PCIE1.A9 PCIE1.A10 PCIE1.B8 PCIE2.A9 PCIE2.A10 PCIE2.B8 PCIE16.A9 PCIE16.A10 PCIE16.B8 PR5204.1 PR5304.1 Q2004.G Q2007.G Q5601.G Q5603.2 Q5603.5 Q5705.D Q9303.1 R449.1 R474.2 R478.2 R525.1 R655.1 R884.1 R888.1 R1009.1 R1505.2 R1532.2 R1534.2 R1535.2 R1536.2 R1613.2 R1614.2 R1809.2 R1810.2 R1811.2 R1812.2 R1814.2 R1815.2 R1901.2 R1902.2 R1905.2 R1907.2 R2004.1 R2005.1 R2011.1 R2015.2 R2024.2 R2210.1 R2212.1 R2605.1 R2610.1 R2633.1 R2711.2 R2920.2 R2931.2 R3115.2 R4310.1 R4693.2 R5204.1 R5601.1 R5610.1 R5611.1 R5614.2 R5711.1 R5712.1 R5713.1 R6405.1 R6409.1 R6801.1 R7928.1 R7950.2 R7958.2 R8000.2 R8001.2 R8015.2 U2701.1 U2701.9
3D3V_S5: C773.1 C774.1 C2038.1 C2308.1 C2310.1 C2311.1 C2313.1 C2317.1 C2318.1 C2501.1 C2723.2 C6110.1 C6111.1 C6112.1 C6113.1 C9321.1 C9322.1 C9404.1 C9405.1 C9411.1 C9412.1 C15159.1 MECLR1.3 NGFFE1.2 NGFFE1.4 NGFFE1.72 NGFFE1.74 PCH1.AD41 PCH1.AJ41 PCH1.AL41 PCH1.AN5 PCH1.BA20 PCH1.BA24 PCH1.BC42 PCH1.BD40 PCH1.W15 PCIE1.B10 PCIE2.B10 PCIE16.B10 PR5009.1 PR5024.1 PR5025.1 PR5108.1 PR5144.1 Q2704.E Q3106.S Q6406.G Q6805.G Q9303.5 Q9303.6 Q9303.7 Q9303.8 R62.1 R63.1 R64.1 R92.2 R93.2 R94.2 R96.2 R98.2 R99.2 R243.2 R244.2 R389.2 R477.1 R479.2 R524.1 R530.1 R979.1 R980.1 R1502.1 R1504.2 R1506.2 R1601.1 R1616.1 R1618.1 R1620.2 R1621.2 R1622.2 R1908.2 R2002.1 R2003.1 R2016.2 R2018.2 R2019.2 R2021.2 R2023.2 R2026.2 R2027.2 R2030.2 R2032.2 R2034.2 R2045.2 R2047.2 R2060.1 R2066.2 R2102.2 R2105.2 R2108.1 R2109.2 R2129.1 R2201.1 R2214.1 R2217.1 R2219.1 R2221.1 R2223.1 R2502.1 R2503.1 R2504.1 R2509.2 R2712.2 R2940.1 R3114.2 R3162.2 R3163.1 R3164.1 R3514.2 R3515.2 R6105.2 R6110.2 R6412.1 R6419.1 R6420.1 R6421.1 R6822.1 R7919.1 R9905.2 R9912.1 R64014.1 RN7901.3(B) RN7901.4(B) RN7905.3(B) RN7905.4(B) SPI1.8 U62.5 U63.5 U2501.8 U4002.1
3D3V_SB: C367.2 C3510.1 C7906.1 C7915.1 C7916.1 C7917.1 L7901.2 Q6401.G Q9303.3 R95.2 R97.2 R507.1 R2514.1 R3402.1 R3405.1 R3406.1 R3407.1 R3514.1 R3515.1 R6403.1 R6407.1 R7938.1 R7947.2 R7948.2 R7949.2 R7961.2 R7965.2 R7966.2 R7967.2 R8013.2 R8014.2 RN7902.3(B) RN7902.4(B) RN7909.3(B) RN7909.4(B) SIO1.4 SIO1.35 SIO1.67 TC5.1 U16.2 U7902.8
3D3V_VCCPGPPA_S5: PCH1.BA31 R2102.1
3D3V_VCCPGPPD_S5: PCH1.BA45 PCH1.BB45 PCH1.BC44 PCH1.BC45 R2129.2
3D3V_VCCPRIM: PCH1.BD3 PCH1.BE3 PCH1.BE4 R2105.1
3D3V_VCCPRTC: C2301.2 PCH1.BA22 R2304.2
3D3V_VDDREGIN_LAN: C3102.1 C3103.1 R3101.1 U3101.23
+PWR_DDR_VTT: PC5009.1 PC5010.1 PR5013.2 PU5002.2 PU5002.20
ANTI-POP_GPIO1: R2710.1 U2701.4
ANTI-POP_GPIO1_L: C2732.1 U2701.3
ANTI-POP_GPIO1_R: Q2702.B R2710.2 R2713.2
ATX_PWRGD_A: Q3515.B R3525.1
AUD_AZACPU_CPU_SDI: CPU1.U1 R702.1
AUD_AZACPU_SCLK: CPU1.V3 R2029.1
AUD_AZACPU_SCLK_R: PCH1.AM2 R2029.2
AUD_AZACPU_SDI: PCH1.AN2 R702.2
AUD_AZACPU_SDO: PCH1.AM1 R2028.2
AUD_AZACPU_SDO_R: CPU1.V2 R2028.1
AUD_IN_L: TC3002.1 U2701.23
AUD_IN_LL: L3002.1 Q3001.6 R3002.2
AUD_IN_LL*: Q3001.2 R3014.2
AUD_IN_LL_1: R3002.1 TC3002.2
AUD_IN_R: TC3003.1 U2701.24
AUD_IN_RR: L3003.1 Q3001.3 R3003.2
AUD_IN_RR*: Q3001.5 R3015.2
AUD_IN_RR_1: R3003.1 TC3003.2
AUD_MIC1_L: TC3005.1 U2701.21
AUD_MIC1_LL: L3001.1 Q3003.6 R3008.2 R3009.2
AUD_MIC1_LL*: Q3003.2 R3018.2
AUD_MIC1_LL_1: R3009.1 TC3005.2
AUD_MIC1_R: TC3006.1 U2701.22
AUD_MIC1_RR: L3006.1 Q3003.3 R3010.2 R3011.2
AUD_MIC1_RR*: Q3003.5 R3019.2
AUD_MIC1_RR_1: R3010.1 TC3006.2
AUD_MIC_1L: AUDR1.2 C3006.1 D3003.2 L3001.2
AUD_MIC_1R: AUDR1.5 C3005.1 D3003.1 L3006.2
AUDAMPIN_L: TC3001.1 U2701.35
AUDAMPIN_L_C: R3004.1 TC3001.2
AUDAMPIN_R: TC3004.1 U2701.36
AUDAMPIN_R_C: R3005.1 TC3004.2
AUDIN_L: AUDR1.32 C3002.1 D3002.2 L3002.2
AUDIN_R: AUDR1.35 C3001.1 D3002.1 L3003.2
AUDIO_VREF: C2733.1 C2734.1 U2701.27
BATLOW_N: PCH1.BD13 R2032.1
BLAN_XTALI: C3101.2 R3111.2 U3101.28 X3101.1
BLAN_XTALO: R3109.2 R3111.1 U3101.29
BLAN_XTALO_1: C3116.2 R3109.1 X3101.3
BLEED: R479.1 R4024.1 U5.5 U5.6
BLEED_EN: R4025.1 R4026.2 U5.2
BOARD_ID_0: PCH1.U35 R1617.1 R1618.2
BOARD_ID_1: PCH1.L44 R1615.1 R1616.2
BOARD_ID_2: PCH1.L43 R1601.2 R1619.1
BPM_CPU_N0: CPU1.D16 XDP1.21
BPM_CPU_N1: CPU1.D17 XDP1.23
BTN_OCL_N: C6406.1 R472.2 R6418.2 SIO1.28
BTN_OCL_R: LEDH2.6 R6418.1 R6419.2
BTN_OCL_SIO_N: R94.1 R473.2 SIO1.22
BV_PS_ON_HEADER_N: ATX1.16 C4302.2 C4303.1 R4305.1
BZ_ON: Q2002.C R2006.1 R2009.1
BZ_ON1: BUZ1.2 R2006.2 R2009.2
CATERR#_CPU: CPU1.D13 TP_CPU_D14.1
CFG0: CPU1.H15 R416.1 R9915.2 XDP1.9
CFG1: CPU1.F15 R418.1 XDP1.11
CFG2: CPU1.F16 R419.1 XDP1.15
CFG3: CPU1.H16 R414.1 R420.1 XDP1.17
CFG4: CPU1.F19 R431.1 XDP1.27
CFG5: CPU1.H18 R429.1 XDP1.29
CFG6: CPU1.G21 R430.1 XDP1.33
CFG7: CPU1.H20 R417.1 XDP1.35
CFG8: CPU1.G16 R426.1 XDP1.10
CFG9: CPU1.E16 R432.1 XDP1.12
CFG10: CPU1.F17 R423.1 XDP1.16
CFG11: CPU1.H17 R428.1 XDP1.18
CFG12: CPU1.G20 R424.1 XDP1.28
CFG13: CPU1.F20 R425.1 XDP1.30
CFG14: CPU1.F21 R427.1 XDP1.34
CFG15: CPU1.H19 R458.1 XDP1.36
CFG_RCOMP: CPU1.M11 R415.1
CLK_CLKIN_SIO: R1911.2 SIO1.37
CLK_LPC_PORT80: DBGH1.6 R1909.2
CLK_LPC_PORT80_R: PCH1.AV19 R1910.1
CLK_PCICLK_SIO: R1910.2 SIO1.47
CLK_PCICLK_SIO_R: PCH1.BC17 R1909.1 R1911.1
CLK_REQ_SATA_N: PCH1.BD25 R1711.2
CLKOUT_48M_R: PCH1.AR17 TP_PCH_AR17.1
CMOS1_3: CMOS1.3 R2054.2
COPEN_N: R2479.1 SIO1.68
CORE_GAP1: PG4702.2 PR4726.1
CORE_GAP2: PG4701.2 PR4728.1
CORE_GAP3: PG4705.2 PR4730.1
CORE_GAP4: PG5203.2 PR4732.1
CPU_BCLK_PCH: CPU1.W5 PCH1.G2
CPU_BCLK_PCH#: CPU1.W4 PCH1.H2
CPU_CLK24M_PCH: CPU1.K9 PCH1.G1
CPU_CLK24M_PCH#: CPU1.J9 PCH1.F1
CPU_FAN_CTRL_CONN: D2601.A FANC1.4 R2605.2 R2607.2
CPU_FAN_PWM1: R2607.1 SIO1.9
CPU_FAN_TACH1: R2604.2 SIO1.8
CPU_FAN_TACH_1: FANC1.3 R2602.2 R2603.1
CPU_FAN_TACH_L: R2603.2 R2604.1 R2606.1
CPU_K12_R_N: PCH1.AB10 R2107.2
CPU_L12_R_P: PCH1.AB11 R2110.2
CPU_PCIBCLK_PCH: CPU1.W1 PCH1.J2
CPU_PCIBCLK_PCH#: CPU1.W2 PCH1.J1
CPU_VCCST_PWRGD: CPU1.U2 Q6404.G R448.1 R449.2 U402.D
CPU_VCCST_PWRGD_Q: Q6404.S R9903.1
CPU_VCCST_PWRGD_Q_PLL: Q6404.D R9912.2
CSN1: PC4628.1 PC4720.2 PG4703.2 PR4611.2 PR4727.1
CSN1A: PC4634.1 PC4812.1 PG4802.2 PR4639.2 PR4821.1
CSN2: PC4606.1 PC4721.2 PG4704.2 PR4623.2 PR4729.1
CSN2A: PC4646.1 PC4813.1 PG4804.2 PR4652.2 PR4823.1
CSN3: PC4605.1 PC4722.2 PG4706.2 PR4622.2 PR4731.1
CSN4: PC4633.1 PC4723.2 PG5204.2 PR4621.2 PR4733.1
CSP1: PC4720.1 PR4726.2 PR4727.2 PU4601.5
CSP1A: PC4812.2 PR4820.2 PR4821.2 PU4601.38
CSP2: PC4721.1 PR4728.2 PR4729.2 PU4601.6
CSP2A: PC4813.2 PR4822.2 PR4823.2 PU4601.37
CSP3: PC4722.1 PR4730.2 PR4731.2 PU4601.2
CSP4: PC4723.1 PR4693.1 PR4732.2 PR4733.2 PU4601.9
CTL1: Q3401.D R3403.2 R3408.1 R3409.2 U3401.6
CTL2: R3406.2 R3411.2 U3401.7
CTL3: R3407.2 SIO1.15 U3401.8
CTRL0: R7961.1 R7974.1 SIO1.2
DAS/DSS#: NGFFM1.10 Q58.G R650.1 R655.2
DDPD_CTRLCLK_PCH: PCH1.BE5 R1613.1
DDPD_CTRLDATA_PCH: PCH1.BE6 R1614.1
DDR_VTT_CNTL: CPU1.AC36 R65.1 R4019.1
DDR_VTT_CNTL_CPU: R62.2 R986.1 R987.1 U2.3
DDR_VTT_CNTL_GATE: R63.2 U2.5 U2.6
DDR_VTT_CNTL_R: R65.2 U2.2
DDSP_D_TX_N0: Q5602.D R5602.2 R5603.2 R5604.2 R5605.2 R5606.2 R5607.2 R5608.2 R5609.2
DDSP_D_TX_N2: Q5602.G R5601.2
DEVSLP: NGFFM1.38 R6215.1
DIMM_CA_CPU_VREF_A_RC: C1134.2 R1123.1
DIMM_CA_VREF_A: C1132.1 C1133.1 C1137.1 C1139.1 C1141.1 DIMM1.146 DIMM3.146 R1125.2 R1126.2
DIMM_CA_VREF_B: C1135.1 C1136.1 C1140.1 C1142.1 C1204.1 C1205.1 DIMM2.146 DIMM4.146 R1201.2 R1206.2
DIMM_DQ_CPU_VREF_B_RC: C1206.2 R1207.1
DIMM_DQ_VREF_B: C1203.1 R1201.1 R1204.2 R1205.2
DISCHARGE_A: Q4301.D R4308.2
DISCHARGE_B: Q4303.D R4309.2
DISCHARGE_C: Q4304.D R4310.2
DISCHARGE_M: Q4301.G Q4302.D Q4303.G Q4304.G R4311.2
DMI_RX_CPU_N0: CPU1.Y4 PCH1.C27
DMI_RX_CPU_N1: CPU1.AA5 PCH1.B28
DMI_RX_CPU_N2: CPU1.AB3 PCH1.B29
DMI_RX_CPU_N3: CPU1.AC5 PCH1.B30
DMI_RX_CPU_P0: CPU1.Y3 PCH1.B27
DMI_RX_CPU_P1: CPU1.AA4 PCH1.A28
DMI_RX_CPU_P2: CPU1.AB4 PCH1.C29
DMI_RX_CPU_P3: CPU1.AC4 PCH1.A30
DMI_TX_CPU_N0: CPU1.AC1 PCH1.L27
DMI_TX_CPU_N1: CPU1.AD2 PCH1.E24
DMI_TX_CPU_N2: CPU1.AE1 PCH1.G27
DMI_TX_CPU_N3: CPU1.AF3 PCH1.L29
DMI_TX_CPU_P0: CPU1.AC2 PCH1.N27
DMI_TX_CPU_P1: CPU1.AD3 PCH1.G24
DMI_TX_CPU_P2: CPU1.AE2 PCH1.E26
DMI_TX_CPU_P3: CPU1.AF2 PCH1.K29
DP1_14: DP1.14 R5710.1
DP1_PWR_CTRL: Q5705.G R97.1 SIO1.57
DP_AUX_CON_N: DP1.17 ED5701.4 ED5701.7 Q5703.6 Q5704.3 R5712.2
DP_AUX_CON_P: DP1.15 ED5701.2 ED5701.9 Q5703.4 Q5704.6 R5714.1
DP_AUX_CPU_N: C5710.1 CPU1.B12
DP_AUX_CPU_N_C: C5710.2 Q5704.4
DP_AUX_CPU_P: C5711.1 CPU1.A12
DP_AUX_CPU_P_C: C5711.2 Q5704.1
DP_CTRLCLK_PCH: PCH1.BB3 Q5703.3 R5711.2
DP_CTRLDATA_PCH: PCH1.BD6 Q5703.1 R5713.2
DP_DATA_CON_N0: DP1.3 ED5703.4 ED5703.7 TR5701.3
DP_DATA_CON_N1: DP1.6 ED5703.1 ED5703.10 TR5702.3
DP_DATA_CON_N2: DP1.9 ED5702.2 ED5702.9 TR5703.3
DP_DATA_CON_N3: DP1.12 ED5702.5 ED5702.6 TR5704.3
DP_DATA_CON_P0: DP1.1 ED5703.5 ED5703.6 TR5701.4
DP_DATA_CON_P1: DP1.4 ED5703.2 ED5703.9 TR5702.4
DP_DATA_CON_P2: DP1.7 ED5702.1 ED5702.10 TR5703.4
DP_DATA_CON_P3: DP1.10 ED5702.4 ED5702.7 TR5704.4
DP_DATA_CPU_N0: C5703.1 CPU1.A18
DP_DATA_CPU_N1: C5705.1 CPU1.E18
DP_DATA_CPU_N2: C5707.1 CPU1.D19
DP_DATA_CPU_N3: C5709.1 CPU1.E20
DP_DATA_CPU_P0: C5702.1 CPU1.B18
DP_DATA_CPU_P1: C5704.1 CPU1.D18
DP_DATA_CPU_P2: C5706.1 CPU1.C19
DP_DATA_CPU_P3: C5708.1 CPU1.D20
DP_DATA_N0: C5703.2 TR5701.2
DP_DATA_N1: C5705.2 TR5702.2
DP_DATA_N2: C5707.2 TR5703.2
DP_DATA_N3: C5709.2 TR5704.2
DP_DATA_P0: C5702.2 TR5701.1
DP_DATA_P1: C5704.2 TR5702.1
DP_DATA_P2: C5706.2 TR5703.1
DP_DATA_P3: C5708.2 TR5704.1
DP_DEVICE_DETECT: Q5702.3 Q5704.2 Q5704.5 R5702.2 R5705.1
DP_DONGLE_DET: DP1.13 ED5701.1 ED5701.10 R5703.2 R5707.1 R5708.1
DP_HPD_CON: DP1.18 ED5701.5 ED5701.6 Q5701.D R5706.1
DP_HPD_PCH: PCH1.AY2 Q5701.S
DPWROK: PCH1.AV11 R2067.2
EAPD_DEPOP: R2713.1 U2701.47
EDP_HPD_PD: PCH1.BD7 R1610.2
EDP_RCOMP_CPU: CPU1.M9 R703.1
EN_VCCSA: R5201.2 U5202.D U5203.G
ENABLE_2540: R3416.2 U3401.5
ESDGND: AUDR1.G1 AUDR1.G2 AUDR1.G3 AUDR1.G4 D3001.1 D3002.3 D3003.3 D3004.1 D3005.3 D3006.1 R2406.2
EVENT#1: DIMM1.78 R1117.2
EVENT#2: DIMM2.78 R1118.2
EVENT#3: DIMM3.78 R1132.2
EVENT#4: DIMM4.78 R1119.2
F_USBEN: R2937.2 R2939.2 R3822.1 U3607.4
F_USBEN2: C3812.1 R3112.1 R3822.2 U3603.4 U3604.4
F_WPWR_USBEN: R2940.2 R2954.2 R2955.2 U3608.4
FB_AUDOUT_L: AUDR1.22 C3004.1 D3005.2 L3004.2
FB_AUDOUT_R: AUDR1.25 C3003.1 D3005.1 L3005.2
FB_AUDOUTR_L: L3004.1 Q3002.6 R3004.2 R3007.1
FB_AUDOUTR_L*: Q3002.2 R3016.2
FB_AUDOUTR_R: L3005.1 Q3002.3 R3005.2 R3006.1
FB_AUDOUTR_R*: Q3002.5 R3017.2
FP_AUDIO_PRESENCE*_C: AUDF1.3 C2932.1 R2931.1 R2934.1
FP_AUDIO_PRESENCE_N: PCH1.AF41 R2934.2
FP_MIC2_L: TC2925.1 U2701.16
FP_MIC2_L_C: R2948.1 TC2925.2
FP_MIC2_R: TC2924.1 U2701.17
FP_MIC2_R_C: R2949.1 TC2924.2
FP_MICVREF_D1: D2906.2 R2932.1
FP_MICVREF_D2: D2906.1 R2941.1
FP_OUT_L: TC2903.1 U2701.14
FP_OUT_L_C: R2945.1 TC2903.2
FP_OUT_LL*: Q2901.2 R2952.2
FP_OUT_R: TC2904.1 U2701.15
FP_OUT_R_C: R2947.1 TC2904.2
FP_OUT_RR*: Q2901.5 R2953.2
FP_OUTR_L: AUDF1.10 C2935.1 FL2908.2
FP_OUTR_LL: FL2908.1 Q2901.6 R2943.1 R2944.2 R2945.2
FP_OUTR_R: AUDF1.6 C2937.1 FL2909.2
FP_OUTR_RR: FL2909.1 Q2901.3 R2942.2 R2946.1 R2947.2
FP_OUTR_SENSE: AUDF1.8 R2908.2 R2936.2
FP_RST_N: LEDH1.7 PCH1.AW1 R2015.1 XDP1.48
FRONT_JD: AUDR1.23 D3004.2 R3012.1
GPD1: PCH1.BB15 R2034.1
GPP_C_5: PCH1.BA40 R2219.2 R2220.2
GPP_H_12: PCH1.BD35 R2223.2 R2224.2
H_PRDY_N: CPU1.B10 R9921.2 XDP1.5
H_PRDY_PCH: PCH1.AT4 R9921.1
H_PREQ_N: CPU1.B9 R404.1 R9920.2 XDP1.3
H_PREQ_PCH: PCH1.AT3 R9920.1
H_PWRGD: C2008.1 CPU1.F8 R2130.2 R9904.1
H_PWRGD_PCH: PCH1.AM3 R2130.1
H_SKTOCC_N: CPU1.AB35 PCH1.Y44 R1620.1
H_TCK: CPU1.F11 R403.1 R2036.1 XDP1.57
H_TDI: CPU1.G12 R452.1 XDP1.56
H_TDO: CPU1.H13 R408.1 R456.1 XDP1.52
H_TMS: CPU1.F13 R454.1 XDP1.58
H_TRST_N: CPU1.F12 R407.1 R455.1
H_TRST_N_R: PCH1.AY5 R9907.1
H_TRST_N_X: R455.2 R9907.2 XDP1.54
HD_LED_PWR: LEDH1.1 R6402.2
HDA_BITCLK_CODEC: C2712.1 R2020.1 U2701.6
HDA_BITCLK_PCH: PCH1.BA9 R2020.2
HDA_RST#_CODEC: R2022.1 R2709.2 U2701.11
HDA_RST#_CODEC_R: Q2705.B R2709.1
HDA_RST#_PCH: PCH1.BD8 R2022.2
HDA_SDIN0_CODEC: R2714.1 U2701.8
HDA_SDIN0_PCH: PCH1.BE7 R2714.2
HDA_SDOUT_CODEC: R2025.1 U2701.5
HDA_SDOUT_PCH: PCH1.BB7 R2025.2 R2058.1
HDA_SDOUT_PCH_R1: MECLR1.2 R2057.2
HDA_SDOUT_PCH_R2: Q2005.C R2056.2 R2057.1 R2058.2
HDA_SYNC_CODEC: R2017.1 U2701.10
HDA_SYNC_PCH: PCH1.BD9 R2017.2
HDMI_CLK_CON: C5613.1 ED5603.1 ED5603.10 HDMI1.15 Q5603.3 R5612.2
HDMI_CLK_PCH: PCH1.BA5 Q5603.4 R5610.2
HDMI_DATA_CMC_N0: C5601.2 EL5603.2 R5603.1
HDMI_DATA_CMC_N1: C5605.2 EL5602.2 R5607.1
HDMI_DATA_CMC_N2: C5603.2 EL5601.2 R5606.1
HDMI_DATA_CMC_N3: C5608.2 EL5604.2 R5609.1
HDMI_DATA_CMC_P0: C5606.2 EL5603.1 R5608.1
HDMI_DATA_CMC_P1: C5604.2 EL5602.1 R5602.1
HDMI_DATA_CMC_P2: C5602.2 EL5601.1 R5605.1
HDMI_DATA_CMC_P3: C5607.2 EL5604.1 R5604.1
HDMI_DATA_CON: C5612.1 ED5603.2 ED5603.9 HDMI1.16 Q5603.6 R5613.2
HDMI_DATA_CON_N0: ED5601.2 ED5601.9 EL5603.3 HDMI1.9
HDMI_DATA_CON_N1: ED5602.5 ED5602.6 EL5602.3 HDMI1.6
HDMI_DATA_CON_N2: ED5602.2 ED5602.9 EL5601.3 HDMI1.3
HDMI_DATA_CON_N3: ED5601.5 ED5601.6 EL5604.3 HDMI1.12
HDMI_DATA_CON_P0: ED5601.1 ED5601.10 EL5603.4 HDMI1.7
HDMI_DATA_CON_P1: ED5602.4 ED5602.7 EL5602.4 HDMI1.4
HDMI_DATA_CON_P2: ED5602.1 ED5602.10 EL5601.4 HDMI1.1
HDMI_DATA_CON_P3: ED5601.4 ED5601.7 EL5604.4 HDMI1.10
HDMI_DATA_CPU_N0: C5601.1 CPU1.A23
HDMI_DATA_CPU_N1: C5605.1 CPU1.E22
HDMI_DATA_CPU_N2: C5603.1 CPU1.D21
HDMI_DATA_CPU_N3: C5608.1 CPU1.D23
HDMI_DATA_CPU_P0: C5606.1 CPU1.B23
HDMI_DATA_CPU_P1: C5604.1 CPU1.D22
HDMI_DATA_CPU_P2: C5602.1 CPU1.C21
HDMI_DATA_CPU_P3: C5607.1 CPU1.C23
HDMI_DATA_PCH: PCH1.BC4 Q5603.1 R5611.2
HDMI_DET_CON: ED5603.4 ED5603.7 HDMI1.19 Q5601.D R5615.2
HDMI_DET_PCH: PCH1.AW4 Q5601.S R5614.1
HDMI_DEVICE_DETECT: Q5702.6 Q5703.2 Q5703.5 R5704.2
HDMI_Q64_PIN5: C5701.1 Q5702.5 R5707.2
HM_VCCP: G7901.2 R7946.1
HM_VCCP_R: C7908.1 R7946.2 SIO1.98
HPGP_M2_SATA_DET#: NGFFM1.69 PU4002.G R6209.1
ILIM_SEL: PCH1.AT43 R3401.1
ILIM_SEL_R: R3401.2 R3405.2 R3410.2 U3401.4
IMVP8_EN_R: R695.1 U27.6
ISO_DET: RN7901.2(A) SIO1.80
ITP_PMODE: PCH1.AT2 R9917.1
JDREF: R2716.1 U2701.40
KA20GATE: R8015.1 SIO1.46
KBRST#: PCH1.AT17 R1907.1 SIO1.45
LAN_CONN_CVT: C3202.1 U2RJ1.R1
LAN_DISABLE_N: PCH1.AR15 R2026.1
LAN_EN_1: C3140.1 Q3107.B R3160.2 R3163.2
LAN_EN_2: Q3107.C R3161.2 R3162.1
LAN_EN_3: C3141.1 Q3106.G R3158.1 R3159.2 R3161.1
LAN_ISOLATE_N: Q3103.3 R3115.1 R3118.2 U3101.20
LAN_LED*: L6801.2 R6824.2 R6825.2
LAN_LED*_EMI: L6801.1 LEDH1.12
LAN_LEDC0: Q6806.C R6825.1
LAN_LEDC1: Q6806.B R6823.2
LAN_LEDC1_E: Q6805.D R6821.2 R6823.1
LAN_LINKACTIVITY_CON_N: ED3204.1 R3206.1 U2RJ1.L3
LAN_LINKACTIVITY_LAN_N: Q6805.S R3206.2 R6822.2 TP_LAN_PIN25.1 U3101.25
LAN_MDI_CON_N0: ED3201.1 EL3204.1 U2RJ1.R3
LAN_MDI_CON_N1: ED3201.4 EL3203.1 U2RJ1.R5
LAN_MDI_CON_N2: ED3203.1 EL3201.1 U2RJ1.R7
LAN_MDI_CON_N3: ED3203.4 EL3202.1 U2RJ1.R9
LAN_MDI_CON_P0: ED3201.6 EL3204.4 U2RJ1.R2
LAN_MDI_CON_P1: ED3201.3 EL3203.4 U2RJ1.R4
LAN_MDI_CON_P2: ED3203.6 EL3201.4 U2RJ1.R6
LAN_MDI_CON_P3: ED3203.3 EL3202.4 U2RJ1.R8
LAN_MDI_LAN_N0: EL3204.2 U3101.2
LAN_MDI_LAN_N1: EL3203.2 U3101.5
LAN_MDI_LAN_N2: EL3201.2 U3101.7
LAN_MDI_LAN_N3: EL3202.2 U3101.10
LAN_MDI_LAN_P0: EL3204.3 U3101.1
LAN_MDI_LAN_P1: EL3203.3 U3101.4
LAN_MDI_LAN_P2: EL3201.3 U3101.6
LAN_MDI_LAN_P3: EL3202.3 U3101.9
LAN_PWR_EN_SIO: R2478.2 SIO1.17
LAN_RSET: R3102.2 U3101.31
LAN_SPEED100_CON_N: ED3204.3 R3205.1 U2RJ1.L1
LAN_SPEED100_LAN_N: C3201.1 R3205.2 TP_LAN_PIN27.1 U3101.27
LAN_SPEED1000_CON_N: ED3204.4 R3204.1 U2RJ1.L2
LAN_SPEED1000_LAN_N: C3206.1 R3204.2 TP_LAN_PIN26.1 U3101.26
LAN_WAKE_N: PCH1.BD11 R2047.1 R3104.2 U3102.D
LAN_WAKEB: R3104.1 R3166.1 U3101.21 U3102.S
LANCLK_REQ_N_R: R3108.1 R3165.2 U3101.12
LDRQ#: R8000.1 SIO1.5
LINE2_JD: AUDF1.9 R2907.2
LINE2_VREFO: D2907.3 U2701.31
LINE2_VREFO_D1: D2907.2 R2942.1
LINE2_VREFO_D2: D2907.1 R2944.1
LINE_SPK_L: C2735.1 U2701.39
LINE_SPK_R: C2736.1 U2701.41
LINEIN_JD: AUDR1.33 D3006.2 R3001.1
LPC_AD_SIO_P0: DBGH1.9 PCH1.AT22 SIO1.41
LPC_AD_SIO_P1: DBGH1.7 PCH1.AV22 SIO1.42
LPC_AD_SIO_P2: DBGH1.3 PCH1.AT19 SIO1.43
LPC_AD_SIO_P3: DBGH1.1 PCH1.BD16 SIO1.44
LPC_FRAME#_SIO: DBGH1.2 PCH1.BE16 R1901.1 SIO1.40
LPC_PME_N: R93.1 R1520.1 SIO1.73
LPC_PME_N_PCH: PCH1.BD17 R1502.2 R1520.2
LPC_PRIQ: PCH1.AW17 R1908.1
LPC_SERIRQ_PCH: PCH1.BA17 R1905.1 SIO1.39
LPSS_GSPI0_MOSI: PCH1.BD28 R2212.2 R2213.2
LPSS_GSPI1_MOSI: PCH1.AT29 R2217.2 R2218.2
M2_CLKREQ#: NGFFM1.52 R6212.1
M2_PERST#: NGFFM1.50 R6213.1
M2_SATA_DET_PCH: PCH1.AG36 PU4002.D R1532.1 R6209.2
M2_WAKE#: NGFFM1.54 R6211.1
M_A_A0: CPU1.AW15 DIMM1.79 DIMM3.79
M_A_A1: CPU1.AU18 DIMM1.72 DIMM3.72
M_A_A2: CPU1.AU17 DIMM1.216 DIMM3.216
M_A_A3: CPU1.AV19 DIMM1.71 DIMM3.71
M_A_A4: CPU1.AT19 DIMM1.214 DIMM3.214
M_A_A5: CPU1.AU20 DIMM1.213 DIMM3.213
M_A_A6: CPU1.AV20 DIMM1.69 DIMM3.69
M_A_A7: CPU1.AU21 DIMM1.211 DIMM3.211
M_A_A8: CPU1.AT20 DIMM1.68 DIMM3.68
M_A_A9: CPU1.AT22 DIMM1.66 DIMM3.66
M_A_A10: CPU1.AY14 DIMM1.225 DIMM3.225
M_A_A11: CPU1.AU22 DIMM1.210 DIMM3.210
M_A_A12: CPU1.AV22 DIMM1.65 DIMM3.65
M_A_A13: CPU1.AV12 DIMM1.232 DIMM3.232
M_A_A14: CPU1.AV14 DIMM1.228 DIMM3.228
M_A_A15: CPU1.AY11 DIMM1.86 DIMM3.86
M_A_A16: CPU1.AW13 DIMM1.82 DIMM3.82
M_A_CKE0: CPU1.AY24 DIMM3.60
M_A_CKE1: CPU1.AW24 DIMM3.203
M_A_CKE2: CPU1.AV24 DIMM1.60
M_A_CKE3: CPU1.AV25 DIMM1.203
M_A_CLK0: CPU1.AW18 DIMM3.74
M_A_CLK1: CPU1.AW17 DIMM3.218
M_A_CLK2: CPU1.AW16 DIMM1.74
M_A_CLK3: CPU1.AT16 DIMM1.218
M_A_CLK#0: CPU1.AV18 DIMM3.75
M_A_CLK#1: CPU1.AY17 DIMM3.219
M_A_CLK#2: CPU1.AV16 DIMM1.75
M_A_CLK#3: CPU1.AU16 DIMM1.219
M_A_CS#0: CPU1.AW12 DIMM3.84
M_A_CS#1: CPU1.AU11 DIMM3.89
M_A_CS#2: CPU1.AV13 DIMM1.84
M_A_CS#3: CPU1.AV10 DIMM1.89
M_A_DQ0: CPU1.AE40 DIMM1.5 DIMM3.5
M_A_DQ1: CPU1.AE37 DIMM1.150 DIMM3.150
M_A_DQ2: CPU1.AG38 DIMM1.12 DIMM3.12
M_A_DQ3: CPU1.AG37 DIMM1.157 DIMM3.157
M_A_DQ4: CPU1.AE39 DIMM1.3 DIMM3.3
M_A_DQ5: CPU1.AE38 DIMM1.148 DIMM3.148
M_A_DQ6: CPU1.AG39 DIMM1.10 DIMM3.10
M_A_DQ7: CPU1.AG40 DIMM1.155 DIMM3.155
M_A_DQ8: CPU1.AJ40 DIMM1.16 DIMM3.16
M_A_DQ9: CPU1.AJ37 DIMM1.161 DIMM3.161
M_A_DQ10: CPU1.AL38 DIMM1.23 DIMM3.23
M_A_DQ11: CPU1.AL37 DIMM1.168 DIMM3.168
M_A_DQ12: CPU1.AJ39 DIMM1.14 DIMM3.14
M_A_DQ13: CPU1.AJ38 DIMM1.159 DIMM3.159
M_A_DQ14: CPU1.AL39 DIMM1.21 DIMM3.21
M_A_DQ15: CPU1.AL40 DIMM1.166 DIMM3.166
M_A_DQ16: CPU1.AN40 DIMM1.27 DIMM3.27
M_A_DQ17: CPU1.AN37 DIMM1.172 DIMM3.172
M_A_DQ18: CPU1.AR38 DIMM1.34 DIMM3.34
M_A_DQ19: CPU1.AR37 DIMM1.179 DIMM3.179
M_A_DQ20: CPU1.AN39 DIMM1.25 DIMM3.25
M_A_DQ21: CPU1.AN38 DIMM1.170 DIMM3.170
M_A_DQ22: CPU1.AR39 DIMM1.32 DIMM3.32
M_A_DQ23: CPU1.AR40 DIMM1.177 DIMM3.177
M_A_DQ24: CPU1.AV37 DIMM1.38 DIMM3.38
M_A_DQ25: CPU1.AW37 DIMM1.183 DIMM3.183
M_A_DQ26: CPU1.AU35 DIMM1.45 DIMM3.45
M_A_DQ27: CPU1.AV35 DIMM1.190 DIMM3.190
M_A_DQ28: CPU1.AU38 DIMM1.36 DIMM3.36
M_A_DQ29: CPU1.AU37 DIMM1.181 DIMM3.181
M_A_DQ30: CPU1.AT35 DIMM1.43 DIMM3.43
M_A_DQ31: CPU1.AW35 DIMM1.188 DIMM3.188
M_A_DQ32: CPU1.AY8 DIMM1.97 DIMM3.97
M_A_DQ33: CPU1.AU8 DIMM1.242 DIMM3.242
M_A_DQ34: CPU1.AV6 DIMM1.104 DIMM3.104
M_A_DQ35: CPU1.AU6 DIMM1.249 DIMM3.249
M_A_DQ36: CPU1.AW8 DIMM1.95 DIMM3.95
M_A_DQ37: CPU1.AV8 DIMM1.240 DIMM3.240
M_A_DQ38: CPU1.AY6 DIMM1.102 DIMM3.102
M_A_DQ39: CPU1.AW6 DIMM1.247 DIMM3.247
M_A_DQ40: CPU1.AV4 DIMM1.108 DIMM3.108
M_A_DQ41: CPU1.AV3 DIMM1.253 DIMM3.253
M_A_DQ42: CPU1.AT3 DIMM1.115 DIMM3.115
M_A_DQ43: CPU1.AT2 DIMM1.260 DIMM3.260
M_A_DQ44: CPU1.AY4 DIMM1.106 DIMM3.106
M_A_DQ45: CPU1.AW4 DIMM1.251 DIMM3.251
M_A_DQ46: CPU1.AT4 DIMM1.113 DIMM3.113
M_A_DQ47: CPU1.AT1 DIMM1.258 DIMM3.258
M_A_DQ48: CPU1.AP1 DIMM1.119 DIMM3.119
M_A_DQ49: CPU1.AP2 DIMM1.264 DIMM3.264
M_A_DQ50: CPU1.AM3 DIMM1.126 DIMM3.126
M_A_DQ51: CPU1.AM2 DIMM1.271 DIMM3.271
M_A_DQ52: CPU1.AP4 DIMM1.117 DIMM3.117
M_A_DQ53: CPU1.AP3 DIMM1.262 DIMM3.262
M_A_DQ54: CPU1.AM4 DIMM1.124 DIMM3.124
M_A_DQ55: CPU1.AM1 DIMM1.269 DIMM3.269
M_A_DQ56: CPU1.AK1 DIMM1.130 DIMM3.130
M_A_DQ57: CPU1.AK2 DIMM1.275 DIMM3.275
M_A_DQ58: CPU1.AH3 DIMM1.137 DIMM3.137
M_A_DQ59: CPU1.AH2 DIMM1.282 DIMM3.282
M_A_DQ60: CPU1.AK4 DIMM1.128 DIMM3.128
M_A_DQ61: CPU1.AK3 DIMM1.273 DIMM3.273
M_A_DQ62: CPU1.AH4 DIMM1.135 DIMM3.135
M_A_DQ63: CPU1.AH1 DIMM1.280 DIMM3.280
M_A_DQS_DN0: CPU1.AF39 DIMM1.152 DIMM3.152
M_A_DQS_DN1: CPU1.AK39 DIMM1.163 DIMM3.163
M_A_DQS_DN2: CPU1.AP39 DIMM1.174 DIMM3.174
M_A_DQS_DN3: CPU1.AU36 DIMM1.185 DIMM3.185
M_A_DQS_DN4: CPU1.AW7 DIMM1.244 DIMM3.244
M_A_DQS_DN5: CPU1.AU3 DIMM1.255 DIMM3.255
M_A_DQS_DN6: CPU1.AN3 DIMM1.266 DIMM3.266
M_A_DQS_DN7: CPU1.AJ3 DIMM1.277 DIMM3.277
M_A_DQS_DP0: CPU1.AF38 DIMM1.153 DIMM3.153
M_A_DQS_DP1: CPU1.AK38 DIMM1.164 DIMM3.164
M_A_DQS_DP2: CPU1.AP38 DIMM1.175 DIMM3.175
M_A_DQS_DP3: CPU1.AV36 DIMM1.186 DIMM3.186
M_A_DQS_DP4: CPU1.AV7 DIMM1.245 DIMM3.245
M_A_DQS_DP5: CPU1.AU2 DIMM1.256 DIMM3.256
M_A_DQS_DP6: CPU1.AN2 DIMM1.267 DIMM3.267
M_A_DQS_DP7: CPU1.AJ2 DIMM1.278 DIMM3.278
M_A_ODT0: CPU1.AW11 DIMM3.87
M_A_ODT1: CPU1.AU14 DIMM3.91
M_A_ODT2: CPU1.AU12 DIMM1.87
M_A_ODT3: CPU1.AY10 DIMM1.91
M_ACT_A_N: CPU1.AU24 DIMM1.62 DIMM3.62
M_ACT_B_N: CPU1.AU28 DIMM2.62 DIMM4.62
M_ALERT_A_N: CPU1.AT23 DIMM1.208 DIMM3.208
M_ALERT_B_N: CPU1.AY25 DIMM2.208 DIMM4.208
M_B_A0: CPU1.AL19 DIMM2.79 DIMM4.79
M_B_A1: CPU1.AL22 DIMM2.72 DIMM4.72
M_B_A2: CPU1.AM22 DIMM2.216 DIMM4.216
M_B_A3: CPU1.AM23 DIMM2.71 DIMM4.71
M_B_A4: CPU1.AP23 DIMM2.214 DIMM4.214
M_B_A5: CPU1.AL23 DIMM2.213 DIMM4.213
M_B_A6: CPU1.AW26 DIMM2.69 DIMM4.69
M_B_A7: CPU1.AY26 DIMM2.211 DIMM4.211
M_B_A8: CPU1.AU26 DIMM2.68 DIMM4.68
M_B_A9: CPU1.AW27 DIMM2.66 DIMM4.66
M_B_A10: CPU1.AP18 DIMM2.225 DIMM4.225
M_B_A11: CPU1.AU27 DIMM2.210 DIMM4.210
M_B_A12: CPU1.AV27 DIMM2.65 DIMM4.65
M_B_A13: CPU1.AR15 DIMM2.232 DIMM4.232
M_B_A14: CPU1.AL17 DIMM2.228 DIMM4.228
M_B_A15: CPU1.AP16 DIMM2.86 DIMM4.86
M_B_A16: CPU1.AN18 DIMM2.82 DIMM4.82
M_B_CKE0: CPU1.AY29 DIMM4.60
M_B_CKE1: CPU1.AV29 DIMM4.203
M_B_CKE2: CPU1.AW29 DIMM2.60
M_B_CKE3: CPU1.AU29 DIMM2.203
M_B_CLK0: CPU1.AM20 DIMM4.74
M_B_CLK1: CPU1.AP22 DIMM4.218
M_B_CLK2: CPU1.AN20 DIMM2.74
M_B_CLK3: CPU1.AP19 DIMM2.218
M_B_CLK#0: CPU1.AM21 DIMM4.75
M_B_CLK#1: CPU1.AP21 DIMM4.219
M_B_CLK#2: CPU1.AN21 DIMM2.75
M_B_CLK#3: CPU1.AP20 DIMM2.219
M_B_CS#0: CPU1.AP17 DIMM4.84
M_B_CS#1: CPU1.AN15 DIMM4.89
M_B_CS#2: CPU1.AN17 DIMM2.84
M_B_CS#3: CPU1.AM15 DIMM2.89
M_B_DQ0: CPU1.AE34 DIMM2.5 DIMM4.5
M_B_DQ1: CPU1.AE35 DIMM2.150 DIMM4.150
M_B_DQ2: CPU1.AH34 DIMM2.12 DIMM4.12
M_B_DQ3: CPU1.AH35 DIMM2.157 DIMM4.157
M_B_DQ4: CPU1.AD34 DIMM2.3 DIMM4.3
M_B_DQ5: CPU1.AD35 DIMM2.148 DIMM4.148
M_B_DQ6: CPU1.AG34 DIMM2.10 DIMM4.10
M_B_DQ7: CPU1.AG35 DIMM2.155 DIMM4.155
M_B_DQ8: CPU1.AL34 DIMM2.16 DIMM4.16
M_B_DQ9: CPU1.AL35 DIMM2.161 DIMM4.161
M_B_DQ10: CPU1.AK31 DIMM2.23 DIMM4.23
M_B_DQ11: CPU1.AL31 DIMM2.168 DIMM4.168
M_B_DQ12: CPU1.AK34 DIMM2.14 DIMM4.14
M_B_DQ13: CPU1.AK35 DIMM2.159 DIMM4.159
M_B_DQ14: CPU1.AK32 DIMM2.21 DIMM4.21
M_B_DQ15: CPU1.AL32 DIMM2.166 DIMM4.166
M_B_DQ16: CPU1.AP35 DIMM2.27 DIMM4.27
M_B_DQ17: CPU1.AN34 DIMM2.172 DIMM4.172
M_B_DQ18: CPU1.AN31 DIMM2.34 DIMM4.34
M_B_DQ19: CPU1.AP31 DIMM2.179 DIMM4.179
M_B_DQ20: CPU1.AN35 DIMM2.25 DIMM4.25
M_B_DQ21: CPU1.AP34 DIMM2.170 DIMM4.170
M_B_DQ22: CPU1.AN32 DIMM2.32 DIMM4.32
M_B_DQ23: CPU1.AP32 DIMM2.177 DIMM4.177
M_B_DQ24: CPU1.AM29 DIMM2.38 DIMM4.38
M_B_DQ25: CPU1.AM28 DIMM2.183 DIMM4.183
M_B_DQ26: CPU1.AR29 DIMM2.45 DIMM4.45
M_B_DQ27: CPU1.AR28 DIMM2.190 DIMM4.190
M_B_DQ28: CPU1.AL29 DIMM2.36 DIMM4.36
M_B_DQ29: CPU1.AL28 DIMM2.181 DIMM4.181
M_B_DQ30: CPU1.AP29 DIMM2.43 DIMM4.43
M_B_DQ31: CPU1.AP28 DIMM2.188 DIMM4.188
M_B_DQ32: CPU1.AR12 DIMM2.97 DIMM4.97
M_B_DQ33: CPU1.AP12 DIMM2.242 DIMM4.242
M_B_DQ34: CPU1.AL13 DIMM2.104 DIMM4.104
M_B_DQ35: CPU1.AL12 DIMM2.249 DIMM4.249
M_B_DQ36: CPU1.AR13 DIMM2.95 DIMM4.95
M_B_DQ37: CPU1.AP13 DIMM2.240 DIMM4.240
M_B_DQ38: CPU1.AM13 DIMM2.102 DIMM4.102
M_B_DQ39: CPU1.AM12 DIMM2.247 DIMM4.247
M_B_DQ40: CPU1.AP9 DIMM2.108 DIMM4.108
M_B_DQ41: CPU1.AR9 DIMM2.253 DIMM4.253
M_B_DQ42: CPU1.AP7 DIMM2.115 DIMM4.115
M_B_DQ43: CPU1.AP6 DIMM2.260 DIMM4.260
M_B_DQ44: CPU1.AP10 DIMM2.106 DIMM4.106
M_B_DQ45: CPU1.AR10 DIMM2.251 DIMM4.251
M_B_DQ46: CPU1.AR7 DIMM2.113 DIMM4.113
M_B_DQ47: CPU1.AR6 DIMM2.258 DIMM4.258
M_B_DQ48: CPU1.AM9 DIMM2.119 DIMM4.119
M_B_DQ49: CPU1.AL9 DIMM2.264 DIMM4.264
M_B_DQ50: CPU1.AL6 DIMM2.126 DIMM4.126
M_B_DQ51: CPU1.AL7 DIMM2.271 DIMM4.271
M_B_DQ52: CPU1.AM10 DIMM2.117 DIMM4.117
M_B_DQ53: CPU1.AL10 DIMM2.262 DIMM4.262
M_B_DQ54: CPU1.AM6 DIMM2.124 DIMM4.124
M_B_DQ55: CPU1.AM7 DIMM2.269 DIMM4.269
M_B_DQ56: CPU1.AJ7 DIMM2.130 DIMM4.130
M_B_DQ57: CPU1.AH6 DIMM2.275 DIMM4.275
M_B_DQ58: CPU1.AF7 DIMM2.137 DIMM4.137
M_B_DQ59: CPU1.AE7 DIMM2.282 DIMM4.282
M_B_DQ60: CPU1.AH7 DIMM2.128 DIMM4.128
M_B_DQ61: CPU1.AJ6 DIMM2.273 DIMM4.273
M_B_DQ62: CPU1.AF6 DIMM2.135 DIMM4.135
M_B_DQ63: CPU1.AE6 DIMM2.280 DIMM4.280
M_B_DQS_DN0: CPU1.AF34 DIMM2.152 DIMM4.152
M_B_DQS_DN1: CPU1.AK33 DIMM2.163 DIMM4.163
M_B_DQS_DN2: CPU1.AN33 DIMM2.174 DIMM4.174
M_B_DQS_DN3: CPU1.AN29 DIMM2.185 DIMM4.185
M_B_DQS_DN4: CPU1.AN13 DIMM2.244 DIMM4.244
M_B_DQS_DN5: CPU1.AR8 DIMM2.255 DIMM4.255
M_B_DQS_DN6: CPU1.AM8 DIMM2.266 DIMM4.266
M_B_DQS_DN7: CPU1.AG6 DIMM2.277 DIMM4.277
M_B_DQS_DP0: CPU1.AF35 DIMM2.153 DIMM4.153
M_B_DQS_DP1: CPU1.AL33 DIMM2.164 DIMM4.164
